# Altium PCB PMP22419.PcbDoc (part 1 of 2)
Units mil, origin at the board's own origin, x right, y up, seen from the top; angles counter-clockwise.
Board outline 4300 x 2100 mil, 4 copper layers (Top Layer, Signal Layer 1, Signal Layer 2, Bottom Layer), stack 66.4 mil thick; 128 components, 54 nets, 301 pads, 317 vias.
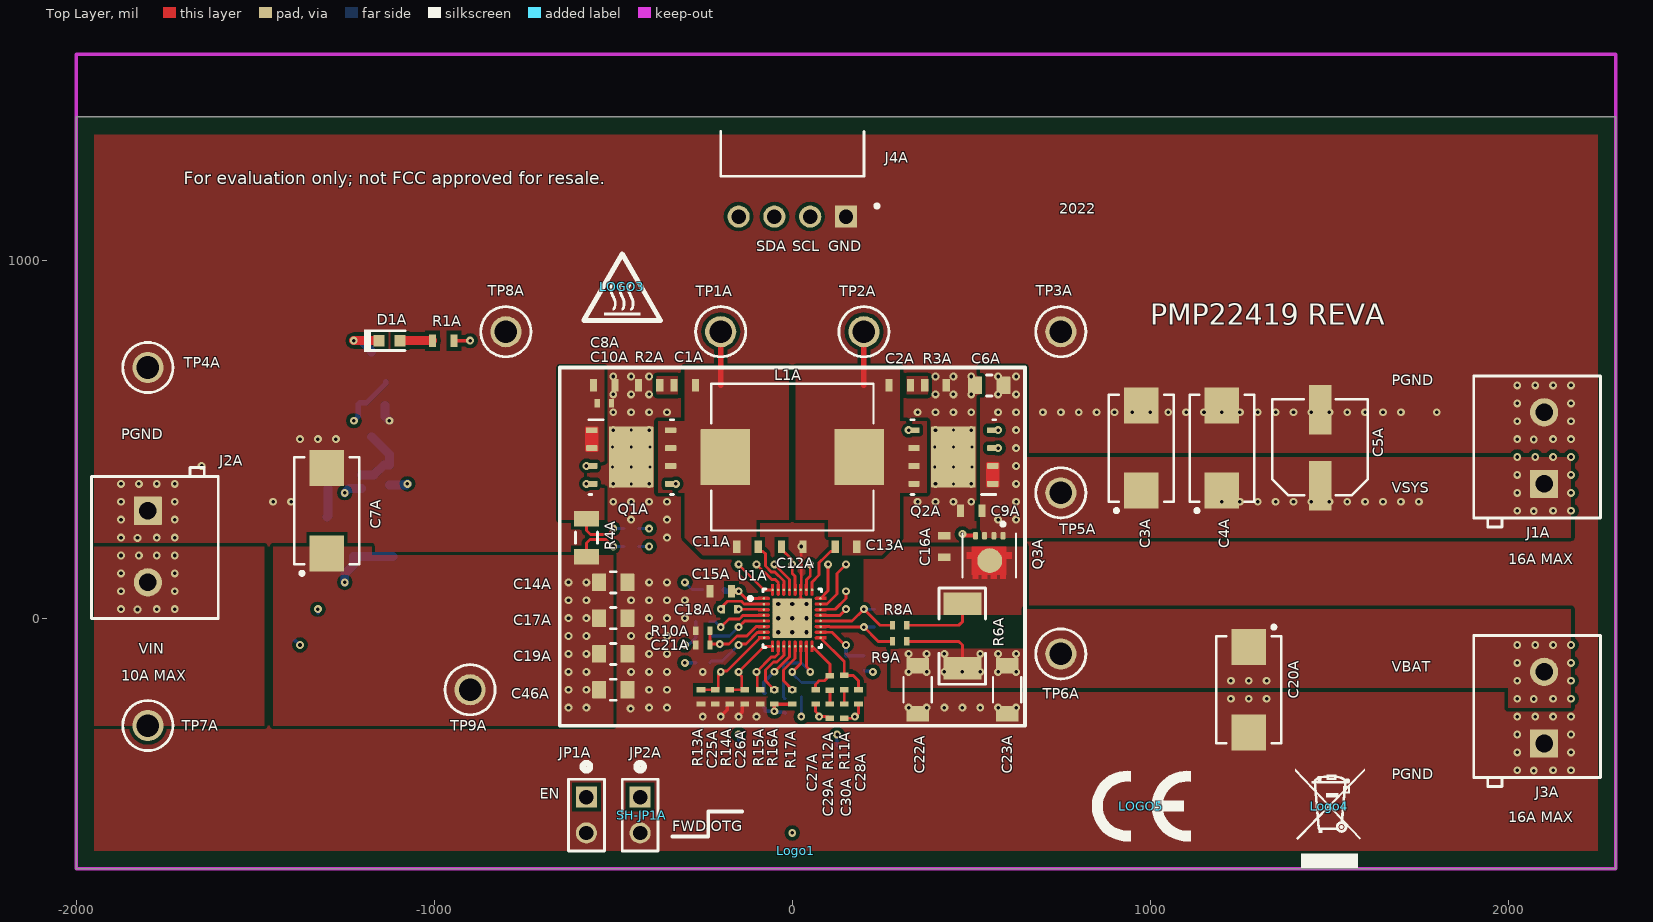
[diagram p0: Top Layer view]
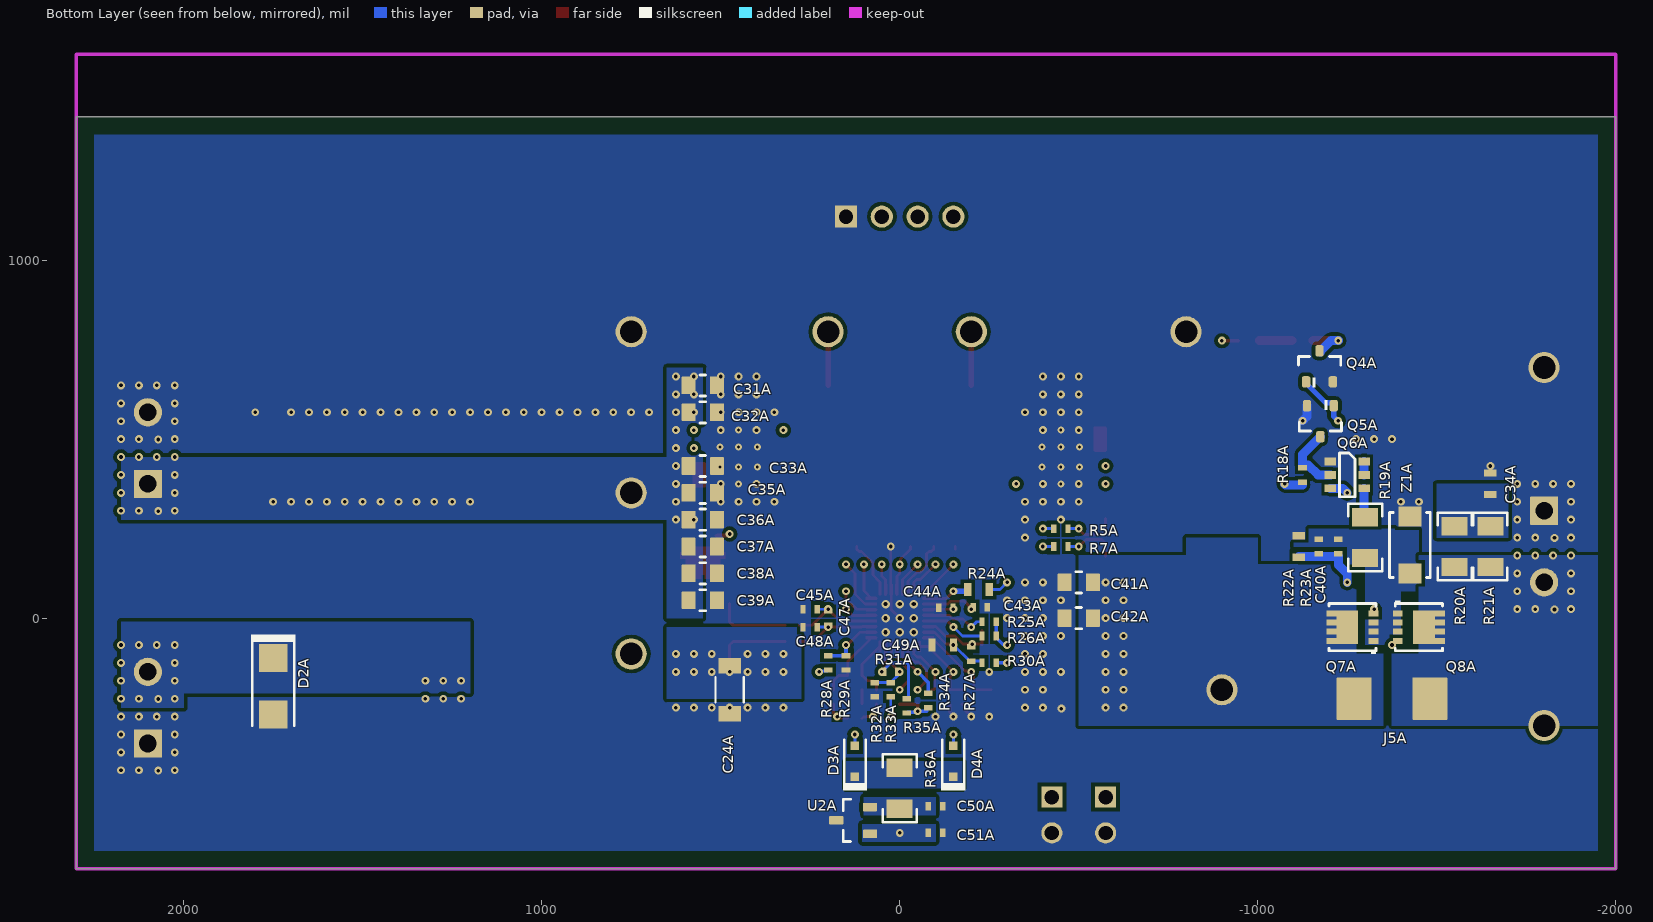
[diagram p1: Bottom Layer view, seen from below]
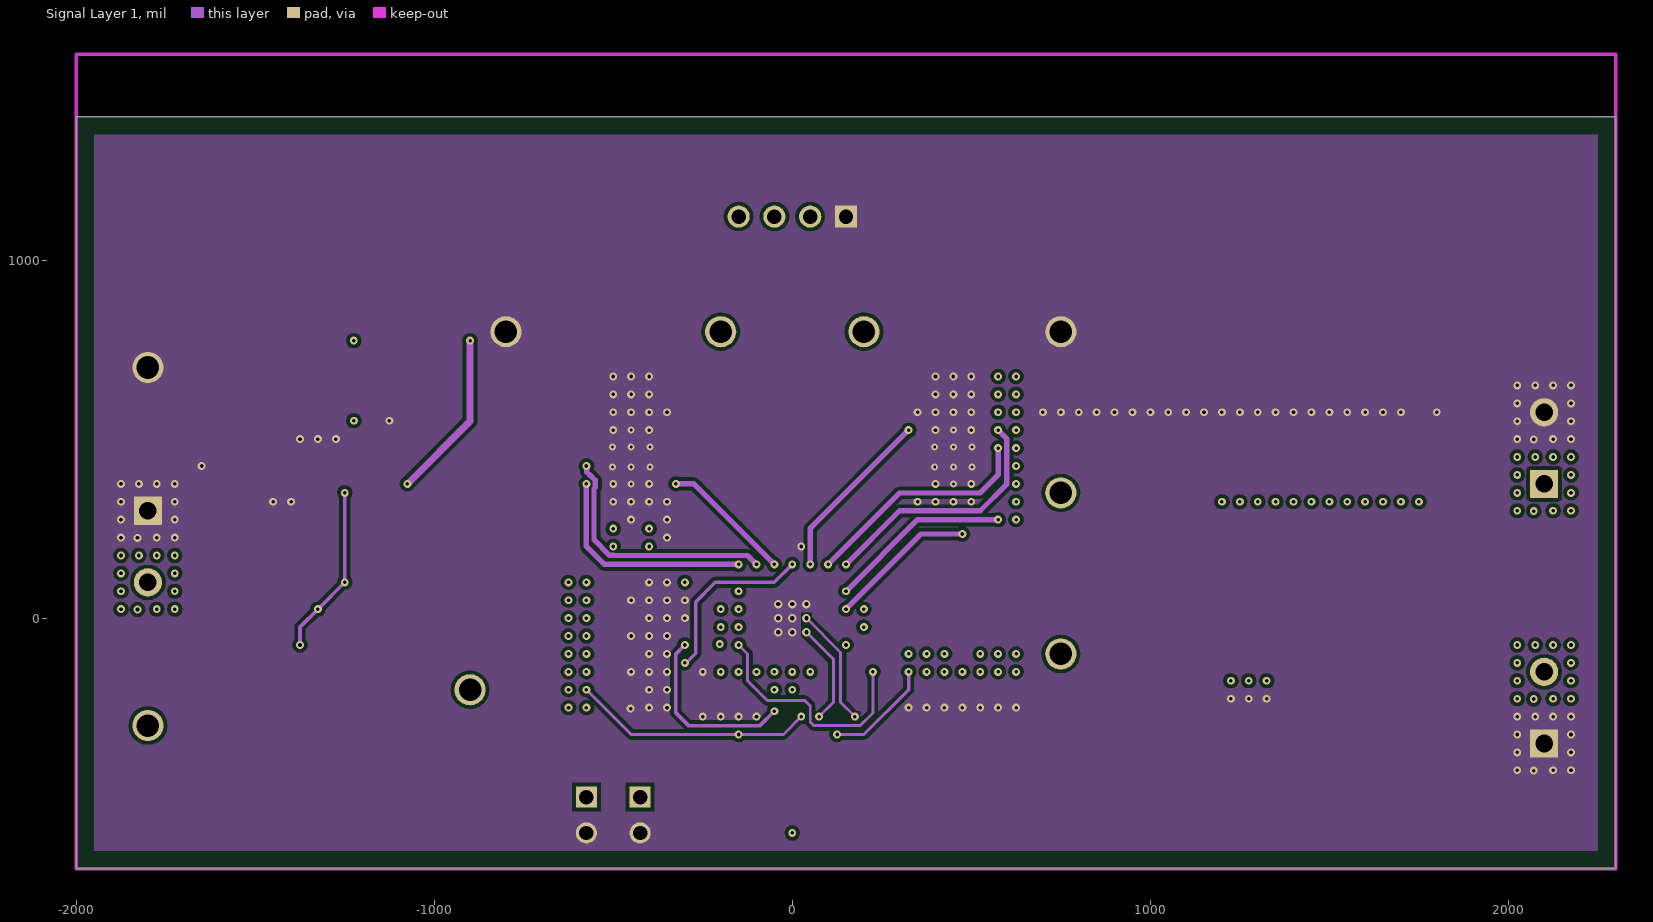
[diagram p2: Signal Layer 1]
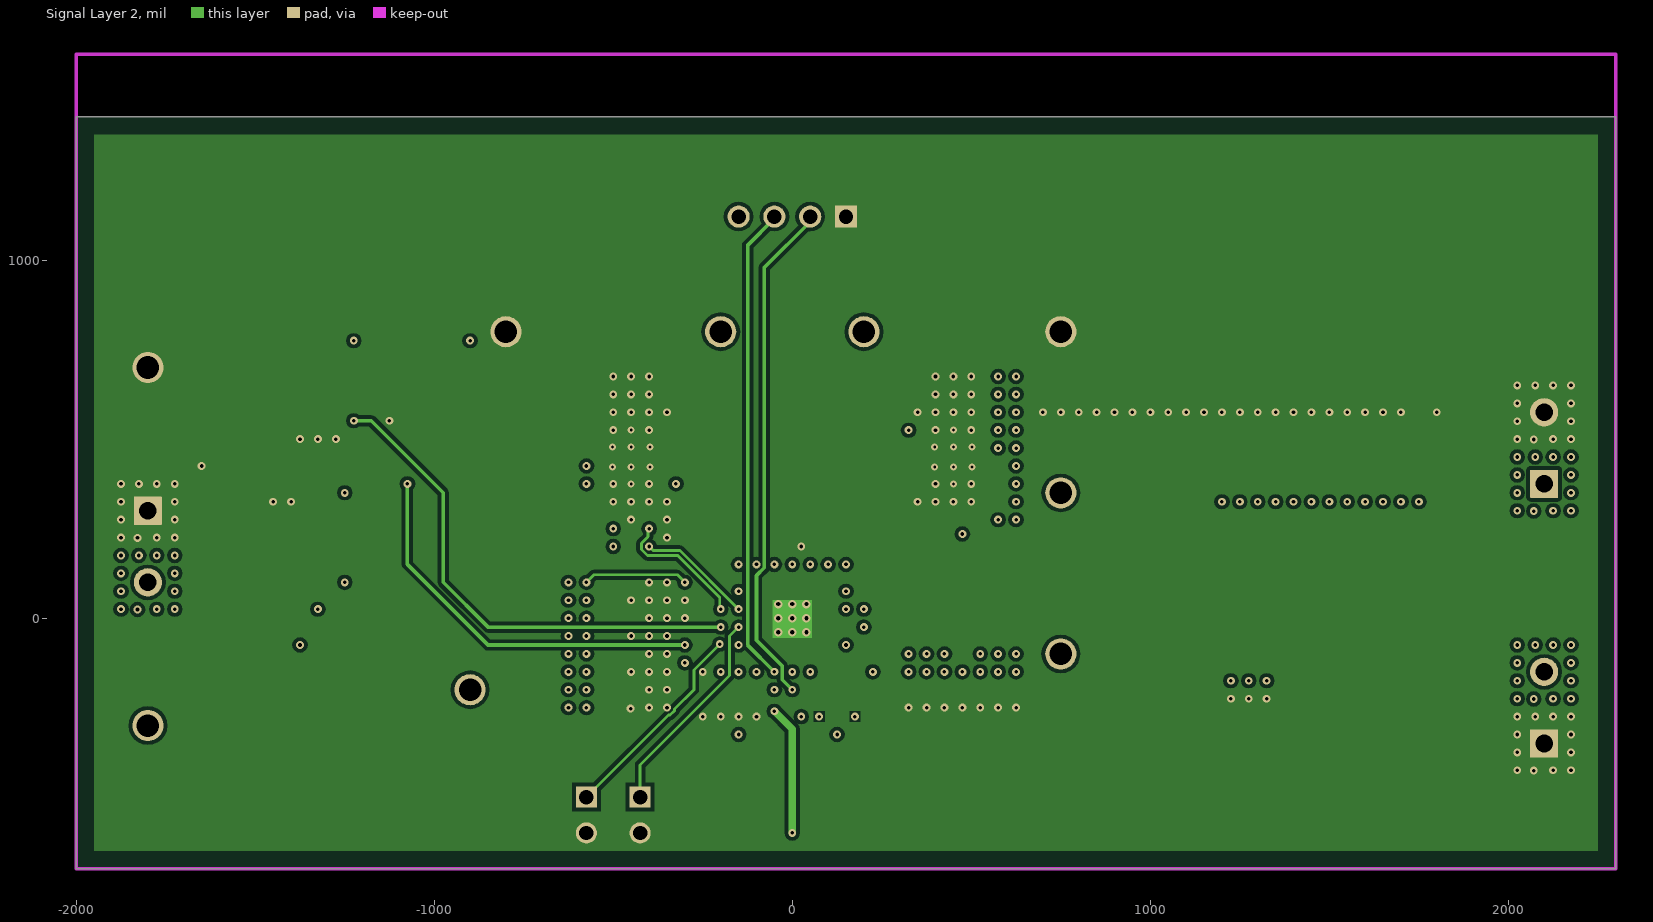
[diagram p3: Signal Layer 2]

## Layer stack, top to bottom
Top Solder: solder mask 0.4, Solder Resist, Dk 3.5
Top Layer: signal copper 2.8
Dielectric1: core 12.6, FR-4 High TG, Dk 4.2
Signal Layer 1: signal copper 2.8
Dielectric 2: prepreg 30, FR-4 High TG, Dk 4.2
Signal Layer 2: signal copper 2.8
Dielectric 3: core 12.6, FR-4 High TG, Dk 4.2
Bottom Layer: signal copper 2.8
Bottom Solder: solder mask 0.4, Solder Resist, Dk 3.5

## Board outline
-2000,1400 -2000,-700 2300,-700 2300,1400

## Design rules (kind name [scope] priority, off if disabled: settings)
AcuteAngle [All] p1: minimum=4.50000000000000E+0001 checktracksonly=FALSE
AssemblyTestPointUsage [All] p1: valid=2
BoardOutlineClearance BoardOutlineClearance_MountingHoles [OnCopper and InComponentClass('Mounting Holes')] p1: gap=39.37 ignorepadtopadclearanceinfootprint=FALSE
BoardOutlineClearance BoardOutlineClearance_Poly [OnCopper and IsPoly] p2: gap=50 ignorepadtopadclearanceinfootprint=FALSE
BoardOutlineClearance [OnCopper and Not InComponentClass('Logo') and not InComponentClass('FiducialMark') and not InRegion(1000,500,4000,800) and not InPoly] p3: gap=75 ignorepadtopadclearanceinfootprint=FALSE
Clearance Clearance_Keepouts [((IsTrack Or IsArc) And Not InPoly) And IsFree and IsKeepOut vs ((IsTrack Or IsArc) And Not InPoly) And IsFree and IsKeepOut] p1: gap=0 ignorepadtopadclearanceinfootprint=FALSE
Clearance Clearance_Poly [InPolygon] p2: gap=10 ignorepadtopadclearanceinfootprint=TRUE
Clearance Clearance_FiducialMark [IsKeepOut and InComponentClass('FiducialMark') vs IsPad and InComponentClass('FiducialMark')] p3: gap=0 ignorepadtopadclearanceinfootprint=FALSE
Clearance [All] p4: gap=6 ignorepadtopadclearanceinfootprint=TRUE
ComponentClearance ComponentClearance_MountingHoles_FiducialMarks [InComponentClass('Mounting Holes') vs InComponentClass('FiducialMark')] p1: gap=50 collisioncheckmode=3 verticalgap=10 showdistances=FALSE
ComponentClearance ComponentClearance_Shunt [InComponentClass('Header') vs InComponentClass('Shunt')] p2: gap=0 collisioncheckmode=3 verticalgap=0 showdistances=FALSE
ComponentClearance ComponentClearance_Logo [InComponentClass('Logo')] p3: gap=50 collisioncheckmode=3 verticalgap=10 showdistances=FALSE
ComponentClearance ComponentClearance_ScrewToNut [(HasFootprint('NY PMS 440 0025 PH')) vs (HasFootprint('Keystone_1902C'))] p4: gap=5 collisioncheckmode=3 verticalgap=10 showdistances=FALSE
ComponentClearance ComponentClearance_MountingHoles [InComponentClass('Mounting Holes')] p5: gap=250 collisioncheckmode=3 verticalgap=100000 showdistances=FALSE
ComponentClearance ComponentClearance_SmallPassives [HasFootprint('0201*') or HasFootprint('0402*') or HasFootprint('0508') or HasFootprint('0603*') or HasFootprint('0612') or HasFootprint('0805*') or HasFootprint('0815*') or HasFootprint('0830*') or HasFootprint('1206*') or HasFootprint('1210*') or HasFootprint('1808*') or HasFootprint('1812*') or HasFootprint('1825*') or HasFootprint('2010*') or HasFootprint('2220*') or HasFootprint('2225*') or HasFootprint('2512*') or HasFootprint('2728*') or HasFootprint('3518*') vs HasFootprint('0201*') or HasFootprint('0402*') or HasFootprint('0508') or HasFootprint('0603*') or HasFootprint('0612') or HasFootprint('0805*') or HasFootprint('0815*') or HasFootprint('0830*') or HasFootprint('1206*') or HasFootprint('1210*') or HasFootprint('1808*') or HasFootprint('1812*') or HasFootprint('1825*') or HasFootprint('2010*') or HasFootprint('2220*') or HasFootprint('2225*') or HasFootprint('2512*') or HasFootprint('2728*') or HasFootprint('3518*')] p6: gap=14.96 collisioncheckmode=3 verticalgap=10 showdistances=FALSE
ComponentClearance ComponentClearance_THtoSMT [IsThruComponent vs IsSMTComponent] p7: gap=40 collisioncheckmode=3 verticalgap=30 showdistances=FALSE
ComponentClearance ComponentClearance_THtoTH [IsThruComponent vs IsThruComponent] p8: gap=30 collisioncheckmode=3 verticalgap=30 showdistances=FALSE
ComponentClearance [All] p9: gap=30 collisioncheckmode=3 verticalgap=10 showdistances=FALSE
DiffPairsRouting [All] p1: maxlimit=100 minlimit=10 mostfreqgap=10 toplayer_minwidth=15 toplayer_maxwidth=15 toplayer_prefwidth=15 midlayer1_minwidth=15 midlayer1_maxwidth=15 midlayer1_prefwidth=15 midlayer2_minwidth=15 midlayer2_maxwidth=15 midlayer2_prefwidth=15 bottomlayer_minwidth=15 bottomlayer_maxwidth=15 bottomlayer_prefwidth=15 maxuncoupledlength=1000
FabricationTestPointUsage TestPointUsage [All] p1: valid=2 allowmultiple=FALSE
FabricationTestpoint Testpoint [All] p1: side=3 testpointundercomponent=TRUE minsize=40 maxsize=100 preferedsize=60 minholesize=0 maxholesize=40 preferedholesize=32 testpointgrid=1 allowsidetop=TRUE allowsidebottom=TRUE usegrid=TRUE gridtolerance=0.01
FanoutControl Fanout_LCC [IsLCC] p1: bgadir=Out bgaviamode=Centered fanoutstyle=Auto fanoutdirection=Alternating viagrid=1 // Fanout_LCC (Default Rule)
FanoutControl Fanout_BGA [IsBGA] p2: bgadir=Out bgaviamode=Centered fanoutstyle=Auto fanoutdirection=Alternating viagrid=1 // Fanout_BGA (Default Rule)
FanoutControl Fanout_Default [All] p4: bgadir=Out bgaviamode=Centered fanoutstyle=Auto fanoutdirection=Alternating viagrid=1 // Fanout_Default (Default Rule)
FanoutControl Fanout_Small [(CompPinCount < 5)] p5: bgadir=Out bgaviamode=Centered fanoutstyle=Auto fanoutdirection=OutThenIn viagrid=1 // Fanout_Small (Default Rule)
HoleSize [All] p1: absolutevalues=TRUE maxlimit=251 minlimit=7.87 maxpercent=80.000 minpercent=20.000
MinimumAnnularRing MinimumAnnularRing_ThermalPadVias [IsVia and InAnyComponent] p1: minimumring=5.91
MinimumAnnularRing [All] p2: minimumring=4
MinimumSolderMaskSliver MinimumSolderMaskSliver_PadPad [IsPad vs IsPad] p1: minsoldermaskwidth=1.5
MinimumSolderMaskSliver MinimumSolderMaskSliver_Via [IsVia] p2: minsoldermaskwidth=1.5
MinimumSolderMaskSliver MinimumSolderMaskSliver_Logo [InComponentClass('Logo') vs InComponentClass('Logo')] p3: minsoldermaskwidth=0.7
MinimumSolderMaskSliver [All] p4: minsoldermaskwidth=3.94
PlaneClearance [All] p1: clearance=10
PlaneConnect [All] p1: planeconnectstyle=Direct reliefexpansion=10 reliefentries=4 reliefconductorwidth=10 reliefairgap=10
PolygonConnect [All] p1: connectstyle=Direct reliefconductorwidth=10 reliefentries=4 polygonreliefangle="90 Angle" airgapwidth=10
RoutingVias ThermalPadVias [IsVia and InAnyComponent] p1: holewidth=7.87 width=19.68 viastyle="Through Hole" minholewidth=7.87 minwidth=19.68 maxholewidth=12.99 maxwidth=23.62
RoutingVias [All] p2: holewidth=10 width=18 viastyle="Through Hole" minholewidth=10 minwidth=18 maxholewidth=40 maxwidth=65
SMDEntry [All] p1 off: side=TRUE corner=FALSE anyangle=FALSE
SMDToCorner [All] p1 off: distance=50000
SilkToBoardRegionClearance [Not ((IsComment or IsDesignator) And (Hide <> 'False')) and not InRegion(1000,500,4000,800)] p1:
SilkToSilkClearance SilkToSilkClearance_Pb-FreeLogo [(HasFootprint('Pb-Free_Overlay_Medium') OR HasFootprint('Pb-Free_Overlay_Small')) vs (HasFootprint('Pb-Free_Overlay_Medium') OR HasFootprint('Pb-Free_Overlay_Small'))] p1: silktosilkclearance=0
SilkToSilkClearance [All] p2: silktosilkclearance=0
SilkToSolderMaskClearance SilkToComponentPadClearance [(IsPad or IsFill or IsRegion) and InAnycomponent] p1: minsilkscreentomaskgap=5 clearancetoexposedcopper=TRUE
SilkToSolderMaskClearance "Silk to Solder Mask Opening" [All] p2: minsilkscreentomaskgap=3.94 clearancetoexposedcopper=FALSE
SolderMaskExpansion [All] p1: expansion=4 istentingtop=FALSE
UnRoutedNet [All] p1: checkbadconnections=TRUE
Width [All] p1: maxlimit=100 minlimit=8 preferedwidth=10 checkconnectedcopper=TRUE
13 further rules are at their usual default settings.

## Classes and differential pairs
component class PMP22419A_MAIN2: C1A C2A C3A C4A C5A C6A C7A C8A C9A C10A C11A C12A C13A C14A C15A C16A C17A C18A C19A C20A C21A C22A C23A C24A C25A C26A C27A C28A C29A C30A C31A C32A C33A C34A C35A C36A C37A C38A C39A C40A C41A C42A C43A C44A C45A C46A C47A C48A C49A C50A C51A D1A D2A D3A D4A J1A J2A J3A J4A J5A JP1A JP2A L1A Q1A Q2A Q3A Q4A Q5A Q6A Q7A Q8A R1A R2A R3A R4A R5A R6A R7A R8A R9A R10A R11A R12A R13A R14A R15A R16A R17A R18A R19A R20A R21A R22A R23A R24A R25A R26A R27A R28A R29A R30A R31A R32A R33A R34A R35A R36A TP1A TP2A TP3A TP4A TP5A TP6A TP7A TP8A TP9A U1A U2A Z1A
component class PMP22419A_Hardware: !PCB1 Logo1 LOGO3 Logo4 LOGO5 SH-JP1A ZZ1 ZZ2 ZZ3 ZZ4
component class AssemblyNote: ZZ1 ZZ2 ZZ3 ZZ4
component class Header: JP1A JP2A
component class Shunt: SH-JP1A

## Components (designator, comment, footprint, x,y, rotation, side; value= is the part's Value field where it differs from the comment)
C1A "Capacitor" 0603S -300,650 r180 top value=330pF
C2A "Capacitor" 0603S 300,650 r0 top value=330pF
C3A "T521D336M035ATE065" 7343-31 975,475 r90 top value=33uF
C4A "T521D336M035ATE065" 7343-31 1200,475 r90 top value=33uF
C5A "Cap_Polarized" CAPSMT_62_F61 1475,475 r90 top value=47uF
C6A "Capacitor" 0805_HV1 550,650 r180 top value=10uF
C7A "T521D336M035ATE065" 7343-31 -1300,300 r90 top value=33uF
C8A "GRM188R71H103KA01D" 0603S -525,650 r0 top value=0.01uF
C9A "GRM188R71H103KA01D" 0603S 500,300 r180 top value=0.01uF
C10A "C1005NP01H102J050BA" 0402S -525,600 r0 top value=1000pF
C11A "Capacitor" 0603S -125,200 r180 top value=0.047uF
C12A "Capacitor" 0603S 0,200 r0 top value=2.2uF
C13A "Capacitor" 0603S 150,200 r0 top value=0.047uF
C14A "Capacitor" 0805_HV1 -500,100 r0 top value=10uF
C15A "C1608X7R1H474K080AC" 0603S -200,75 r180 top value=0.47uF
C16A "Capacitor" 0603S 425,200 r90 top value=1uF
C17A "Capacitor" 0805_HV1 -500,0 r0 top value=10uF
C18A "0402B103K500CT" 0402S -175,25 r180 top value=0.01uF
C19A "Capacitor" 0805_HV1 -500,-100 r0 top value=10uF
C20A "T521D336M035ATE065" 7343-31 1275,-200 r270 top value=33uF
C21A "04025A101FAT2A" 0402S -250,-75 r180 top value=100pF
C22A "Capacitor" 1206_180 350,-200 r270 top value=10uF
C23A "Capacitor" 1206_180 600,-200 r270 top value=10uF
C24A "Capacitor" 1206_180 475,-200 r270 bottom value=10uF
C25A "04025A101FAT2A" 0402S -215,-220 r270 top value=100pF
C26A "04025A101FAT2A" 0402S -133.19,-220 r270 top value=100pF
C27A "Capacitor" 0402S 65,-220 r90 top value=33pF
C28A "Capacitor" 0402S 185,-220 r270 top value=15pF
C29A "GRM155R71H332KA01D" 0402S 105,-260 r90 top value=3300pF
C30A "C0402C122J5GACTU" 0402S 145,-260 r270 top value=1200pF
C31A "Capacitor" 0805_HV1 550,650 r180 bottom value=10uF
C32A "Capacitor" 0805_HV1 550,575 r180 bottom value=10uF
C33A "Capacitor" 0805_HV1 550,425 r180 bottom value=10uF
C34A "Capacitor" 0603S -1650,375 r90 bottom value=1uF
C35A "Capacitor" 0805_HV1 550,350 r180 bottom value=10uF
C36A "Capacitor" 0805_HV1 550,275 r180 bottom value=10uF
C37A "Capacitor" 0805_HV1 550,200 r180 bottom value=10uF
C38A "Capacitor" 0805_HV1 550,125 r180 bottom value=10uF
C39A "Capacitor" 0805_HV1 550,50 r180 bottom value=10uF
C40A "0402BB104KW500" 0402S -1225,200 r90 bottom value=0.1uF
C41A "Capacitor" 0805_HV1 -500,100 r0 bottom value=10uF
C42A "Capacitor" 0805_HV1 -500,0 r0 bottom value=10uF
C43A "CGA2B3X7R1H333K050BB" 0402S -225,30 r180 bottom value=0.033uF
C44A "CGA2B3X7R1H333K050BB" 0402S -129,29.18 r0 bottom value=0.033uF
C45A "GRM155R71H183KA12D" 0402S 250,25 r0 bottom value=0.018uF
C46A "Capacitor" 0805_HV1 -500,-200 r0 top value=10uF
C47A "CGA2B3X7R1H683K050BB" 0402S 200,0 r90 bottom value=0.068uF
C48A "GRM155R71H183KA12D" 0402S 250,-25 r0 bottom value=0.018uF
C49A "Capacitor" 0603S -120,-75 r0 bottom value=1uF
C50A "0402BB104KW500" 0402S -100,-525 r0 bottom value=0.1uF
C51A "0402BB104KW500" 0402S -100,-600 r0 bottom value=0.1uF
D1A "LTST-C190GKT" LED_LTST-C190 -1125,775 r180 top value=Green
D2A "20V" SMA 1750,-190 r270 bottom
D3A "BAT54HT1G" SOD-323 125,-400 r90 bottom value=30V
D4A "BAT54HT1G" SOD-323 -150,-400 r90 bottom value=30V
J1A "Receptacle_2x1" On-Shore_ED120_2DS 2100,475 r90 top
J2A "Receptacle_2x1" On-Shore_ED120_2DS -1800,200 r270 top
J3A "Receptacle_2x1" On-Shore_ED120_2DS 2100,-250 r90 top
J4A "22-05-3041" FP-22-05-3041_HDR4-MFG 0,1400 r180 top
J5A "5102" Keystone_5102 -1375,-225 r0 bottom
JP1A "Header_2x1" CONN_5-146261-1 -575,-550 r270 top
JP2A "Header_2x1" CONN_5-146261-1 -425,-550 r270 top
L1A "Inductor_Iron" FP-BMRHDY1010302R2MA1_SMT_IND_11MM2_10MM1-MFG 0,450 r0 top
Logo1 "FCC disclaimer" FCC_disclaimer 10,-650 r0 top
LOGO3 "CAUTION HOT SURFACE" IEC_HotSurface_Small -475,925 r0 top
Logo4 "WEEE logo" WEEE_Minimum 1500,-525 r0 top
LOGO5 "CE Mark" CE_Mark_5mm 975,-525 r0 top
Q1A "CSD87355Q5D" DQY0008A -450,450 r0 top value=30V
Q2A "CSD87355Q5D" DQY0008A 450,450 r180 top value=30V
Q3A "AONR21307" FP-AONR21307_DFN8-MFG 550,175 r180 top
Q4A "MOSFET_N_D3G1S2" SOT-23L -1172.6,703.31 r90 bottom value=60V
Q5A "MOSFET_N_D3G1S2" SOT-23L -1175,550 r270 bottom value=60V
Q6A "DCX124EK-7-F" SC-74R -1250,400 r180 bottom value="50 V"
Q7A "DMP3035SFG-7" PowerDI3333-8 -1264.76,-25 r0 bottom value=-30V
Q8A "DMP3035SFG-7" PowerDI3333-8 -1450,-25 r180 bottom value=-30V
R1A "Resistor" 0603S -975,775 r0 top value=2.00k
R2A "Resistor" 0603S -400,650 r0 top value=56
R3A "Resistor" 0603S 400,650 r180 top value=56
R4A "WSLP12065L000FEA" 1206L -575,225 r90 top value=0.005
R5A "CRCW04024R99FKED" 0402S -450,250 r180 bottom value=4.99
R6A "CSNL2010FT5L00" 2010 475,-50 r270 top value=0.005
R7A "CRCW04024R99FKED" 0402S -450,200 r180 bottom value=4.99
R8A "CRCW040210R0FKED" 0402S 300,-20 r0 top value=10.0
R9A "CRCW040210R0FKED" 0402S 300,-65 r0 top value=10.0
R10A "RC0402FR-07220KL" 0402S -250,-35 r180 top value=220k
R11A "Resistor" 0402S 145,-180 r270 top value=10.0k
R12A "CRCW040216K9FKED" 0402S 105,-181.1 r90 top value=16.9k
R13A "CRCW0402105KFKED" 0402S -255,-220 r90 top value=105k
R14A "CRCW0402100KFKED" 0402S -175,-220 r90 top value=100k
R15A "CRCW040230K1FKED" 0402S -90,-220 r270 top value=30.1k
R16A "CRCW040210K0FKED" 0402S -50,-220 r90 top value=10.0k
R17A "CRCW040210K0FKED" 0402S 0,-220 r270 top value=10.0k
R18A "CRCW040210K0FKED" 0402S -1125,400 r270 bottom value=10.0k
R19A "ERJ-8ENF10R0V" 1206 -1300,225 r270 bottom value=10.0
R20A "Resistor" 1206 -1550,200 r270 bottom value=3.9
R21A "Resistor" 1206 -1650,200 r270 bottom value=3.9
R22A "CRCW060320K0FKEA" 0603S -1115,200 r270 bottom value=20.0k
R23A "CRCW0402100KFKED" 0402S -1170,200 r90 bottom value=100k
R24A "CRCW06031R00JNEA" 0603S -220,80 r0 bottom value=1.0
R25A "CRCW040210K0FKED" 0402S -250,-10 r180 bottom value=10.0k
R26A "CRCW040210K0FKED" 0402S -250,-50 r0 bottom value=10.0k
R27A "CRCW0402383KFKED" 0402S -200,-100 r270 bottom value=383k
R28A "RC0402FR-0733KL" 0402S 200,-125 r270 bottom value=33.0k
R29A "CRCW0402100KFKED" 0402S 150,-125 r90 bottom value=100k
R30A "CRCW040210R0FKED" 0402S -250,-125 r0 bottom value=10.0
R31A "CRCW04022M00JNED" 0402S 25,-150 r0 bottom value=2.0Meg
R32A "CRCW0402100KFKED" 0402S 70,-200 r90 bottom value=100k
R33A "CRCW0402100KFKED" 0402S 25,-200 r270 bottom value=100k
R34A "CRCW040210K0FKED" 0402S -80,-230 r270 bottom value=10.0k
R35A "CRCW040210K0FKED" 0402S -20,-245 r90 bottom value=10.0k
R36A "ERJ-8ENF10R0V" 1206 0,-475 r90 bottom value=10.0
SH-JP1A "SNT-100-BK-G" SNT-100-BK-G -420,-550 r90 top value=1x2
TP1A "5012" Keystone5012 -200,800 r90 top
TP2A "5012" Keystone5012 200,800 r90 top
TP3A "5011" Keystone5011 750,800 r180 top
TP4A "5011" Keystone5011 -1800,700 r180 top
TP5A "5010" Keystone5010 750,350 r0 top
TP6A "5010" Keystone5010 750,-100 r0 top
TP7A "5010" Keystone5010 -1800,-300 r0 top
TP8A "5011" Keystone5011 -800,800 r180 top
TP9A "5010" Keystone5010 -900,-200 r0 top
U1A "BQ25720RSN" RSN0032B-MFG 0,0 r0 top
U2A "PM-REG-LM3480-SOT3" DBZ0003A_N 130,-565 r0 bottom
Z1A "SMAJ26CA" SMA_Bi -1425,204.33 r90 bottom value=26V
ZZ1 "This Assembly Note is for PCB labels only" AssemblyNoteLabel -1785,2138 r0 top
ZZ2 "These assemblies are ESD sensitive, ESD precautions shall be observed." AssemblyNote -1785,2029.11 r0 top
ZZ3 "These assemblies must be clean and free from flux and all contaminants. Use of no clean flux is not acceptable." AssemblyNote -1785,1940.56 r0 top
ZZ4 "These assemblies must comply with workmanship standards IPC-A-610 Class 2, unless otherwise specified." AssemblyNote -1785,1852 r0 top

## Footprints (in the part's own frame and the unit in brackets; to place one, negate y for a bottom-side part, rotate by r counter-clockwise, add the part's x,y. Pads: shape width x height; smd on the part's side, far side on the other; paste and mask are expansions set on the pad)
0402S [mil] "Based on C0402S footprint from PADS legacy"
  rect 15x24 smd: 1(-20,0) 2(20,0)
  body extent -22,-12 22,12, height 24
0603S [mil]
  rect 20x35 smd: 1(-30,0) 2(30,0)
  body extent -34,-19 34,19, height 39
0805_HV1 [mm] "Custom footprint based on analyzing multiple manufacturer recommendations"
  rrect10% 1x1.25 smd: 1(-1,0) 2(1,0)
  silkscreen extent -0.2,-0.75 0.2,0.75, body extent -1.1,-0.72 1.1,0.73, height 1.45
1206 [mm] "1206 from SM-752 data"
  rect 1.3x1.85 smd: 1(-1.45,0) 2(1.45,0)
  silkscreen extent -2.4,-1.21 2.4,1.21, body extent -1.7,-0.9 1.7,0.9, height 1.35
1206_180 [mm] "1206_180"
  rect 1.1x1.6 smd: 1(-1.7,0) 2(1.7,0)
  silkscreen extent -0.9,-1 0.9,1, body extent -1.75,-0.95 1.75,0.95, height 1.8
1206L [mm] "1206 from SM-752 data"
  rect 1.1x1.75 smd: 1(-1.35,0) 2(1.35,0)
  silkscreen extent -0.4,-0.77 0.4,0.77, body extent -1.7,-0.9 1.7,0.9, height 1.35
2010 [mm] "Chip Capacitor, Body 5.08x2.54mm, IPC Medium Density"
  rect 1.6x2.7 smd: 1(-2.3,0) 2(2.3,0)
  silkscreen extent -3.42,-1.65 3.42,1.65, body extent -2.73,-1.45 2.73,1.45, height 1.66
7343-31 [mm] "Medium Density based on Kemet T495 dimensions"
  rect 2.55x2.45 smd: 1(-3.025,0) 2(3.025,0)
  silkscreen extent -4.56,-2.3 3.8,2.3, body extent -3.8,-2.3 3.8,2.3, height 3.1
AssemblyNote [mil] "Assembly Note"
AssemblyNoteLabel [mil] "Assembly Note for PCB Labels"
CAPSMT_62_F61 [mm] "6.3 x 5.8mm:  Chemi-Con F61"
  rect 3.5x1.6 smd: 1(-2.675,0.025) 2(2.725,0.025)
  silkscreen extent -3.34,-3.38 3.46,3.42, body extent -3.37,-3.38 3.46,3.43, height 6.1
CE_Mark_5mm [mil] "Minimum text height for CE Mark"
  silkscreen extent -138,-98 138,98
CONN_5-146261-1 [mm] "Sullins"
  rect 1.5x1.5 hole 1.02: 1(-1.27,0)
  round 1.5 hole 1.02: 2(1.27,0)
  silkscreen extent -3.68,-1.27 2.54,1.27, body extent -2.51,-1.27 2.51,1.27, height 10.87
DBZ0003A_N [mm] "SOT23, 3-Leads, Body 2.9x1.3mm, Pitch 0.95mm, Lead Span 2.4mm, IPC Medium Density"
  rrect17% 1x0.6 smd: 1(-1.2,0.95) 2(-1.2,-0.95) 3(1.2,0)
  silkscreen extent 0.2,-1.5 0.7,1.5, body extent -1.26,-1.46 1.26,1.46, height 0.98
DQY0008A [mm] "LSON-CLIP-8"
  rrect24% 0.81x0.41 smd mask+0: 1(-2.795,1.905) 2(-2.795,0.635)
  rrect24% 0.81x0.41 smd: 3(-2.795,-0.635) 4(-2.795,-1.905) 5(2.795,-1.905) 6(2.795,-0.635) 8(2.795,1.905)
  rrect24% 0.81x0.41 smd mask+0.102: 7(2.795,0.635)
  rrect3% 3.156x4.319 smd paste-2.217: 9(0,0)
  Top Layer region: -3.25,0.48 -3.25,2.06 -3.237,2.11 -3.2,2.147 -3.15,2.16 -3.15,2.16 -2.44,2.16 -2.402,2.152 -2.369,2.131 -2.348,2.098 -2.34,2.06 -2.34,2.06 -2.34,0.48 -2.348,0.442 -2.369,0.409 -2.402,0.388 -2.44,0.38 -2.44,0.38 -3.15,0.38 -3.188,0.388 -3.221,0.409 -3.242,0.442 -3.25,0.48
  silkscreen extent -3,-2.65 3,2.65, body extent -3,-2.5 3,2.5, height 1.6
FCC_disclaimer [mil]
FP-22-05-3041_HDR4-MFG [mm]
  rrect6% 1.57x1.57 hole 1.02 paste-1000 mask+0: 1(-3.81,7.073)
  round 1.57 hole 1.02 paste-1000 mask+0: 2(-1.27,7.073) 3(1.27,7.073) 4(3.81,7.073)
  silkscreen extent -6.13,1.03 5.08,6.44, body extent -5.18,-6.28 5.18,7.96, height 0.25
FP-AONR21307_DFN8-MFG [mm]
  rrect29% 0.35x0.5 smd paste+0 mask+0: 1(-0.975,-1.4) 2(-0.325,-1.4) 3(0.325,-1.4) 4(0.975,-1.4)
  round 1.769 smd paste+0 mask+0: 5-6-7-8(-0.038,0.367)
  Top Layer region: -1.225,-0.63 -1.225,-0.215 -1.605,-0.215 -1.605,0.215 -1.225,0.215 -1.225,1.35 -1.175,1.35 -1.175,1.65 -0.775,1.65 -0.775,1.35 -0.525,1.35 -0.525,1.65 -0.125,1.65 -0.125,1.35 0.125,1.35 0.125,1.65 0.525,1.65 0.525,1.35 0.775,1.35 0.775,1.65 1.175,1.65 1.175,1.35 1.225,1.35 1.225,0.215 1.605,0.215 1.605,-0.215 1.225,-0.215 1.225,-0.63
  silkscreen extent -1.9,-2.35 1.9,1.55, body extent -1.71,-1.75 1.71,1.75, height 0.25
FP-BMRHDY1010302R2MA1_SMT_IND_11MM2_10MM1-MFG [mm]
  rrect3% 3.5x4 smd paste+0 mask+0: 1(-4.75,0) 2(4.75,0)
  silkscreen extent -5.75,-5.2 5.75,5.2, body extent -6.6,-5.3 6.6,5.3, height 0.25
IEC_HotSurface_Small [mil]
  silkscreen extent -107,-93 107,92
Keystone5010 [mil] "Keystone Multipurpose loops"
  round 87 hole 63: 1(0,0)
  silkscreen extent -70,-70 70,70, body extent -63,-63 63,62, height 319
Keystone5011 [mil] "Keystone Multipurpose loops"
  round 87 hole 63: 1(0,0)
  silkscreen extent -70,-70 70,70, body extent -63,-63 63,62, height 319
Keystone5012 [mil] "Keystone Multipurpose loops"
  round 87 hole 63: 1(0,0)
  silkscreen extent -70,-70 70,70, body extent -63,-63 63,62, height 319
Keystone_5102 [mm] "Shorting Jumper, 5.375mm, 2 Position, SMT"
  rrect4% 2.475x3 smd: 1(-2.688,0) 2(2.688,0)
  body extent -3.42,-1.19 3.43,1.35, height 1
LED_LTST-C190 [mm] "Lite-On"
  rect 0.8x0.8 smd: 1(-0.75,0) 2(0.75,0)
  silkscreen extent -1.1,-0.8 1.8,0.8, body extent -0.85,-0.45 0.85,0.45, height 0.9
On-Shore_ED120_2DS [mm] "ONSHORE"
  rrect5% 2x2 hole 1.25: 1(-2.54,0)
  round 2 hole 1.25: 2(2.54,0)
  silkscreen extent -5.6,-4 5.12,5, body extent -5.78,-4 5.08,5, height 13
PowerDI3333-8 [mm] "SMD, 8-Leads, Body 3.3x3.3mm, Pitch 0.65mm"
  rect 0.7x0.42 smd: 1(-1.5,0.975) 2(-1.5,0.325) 3(-1.5,-0.325) 4(-1.5,-0.975) 5(1.5,-0.975) 6(1.5,-0.325) 7(1.5,0.325) 8(1.5,0.975)
  rect 1.55x2.37 smd: 9(0.375,0)
  silkscreen extent -1.68,-1.68 1.68,1.9, body extent -1.68,-1.68 1.68,1.68, height 0.86
RSN0032B-MFG [mm]
  round 0.18 smd paste+0 mask+0: 1(-2.01,1.4) 2(-2.01,1) 3(-2.01,0.6) 4(-2.01,0.2) 5(-2,-0.2) 6(-2,-0.6) 7(-2,-1) 8(-2,-1.4) 9(-1.4,-2.01) 10(-1,-2.01) 11(-0.6,-2.01) 12(-0.2,-2.01) 13(0.2,-2) 14(0.6,-2) 15(1,-2) 16(1.4,-2) 17(2.01,-1.4) 18(2.01,-1) 19(2.01,-0.6) 20(2.01,-0.2) 21(2,0.2) 22(2,0.6) 23(2,1) 24(2,1.4) 25(1.4,2.01) 26(1,2.01) 27(0.6,2.01) 28(0.2,2.01) 29(-0.2,2) 30(-0.6,2) 31(-1,2) 32(-1.4,2)
  rrect4% 2.8x2.8 smd paste-1000 mask+0: 33(0,0)
  Top Layer region: -2.4,1.5 -1.7,1.5 -1.662,1.492 -1.629,1.471 -1.608,1.438 -1.6,1.4 -1.6,1.4 -1.608,1.362 -1.629,1.329 -1.662,1.308 -1.7,1.3 -1.7,1.3 -2.4,1.3
  Top Layer region: -2.4,1.1 -1.7,1.1 -1.662,1.092 -1.629,1.071 -1.608,1.038 -1.6,1 -1.6,1 -1.608,0.962 -1.629,0.929 -1.662,0.908 -1.7,0.9 -1.7,0.9 -2.4,0.9
  Top Layer region: -2.4,0.7 -1.7,0.7 -1.662,0.692 -1.629,0.671 -1.608,0.638 -1.6,0.6 -1.6,0.6 -1.608,0.562 -1.629,0.529 -1.662,0.508 -1.7,0.5 -1.7,0.5 -2.4,0.5
  Top Layer region: -2.4,0.3 -1.7,0.3 -1.662,0.292 -1.629,0.271 -1.608,0.238 -1.6,0.2 -1.6,0.2 -1.608,0.162 -1.629,0.129 -1.662,0.108 -1.7,0.1 -1.7,0.1 -2.4,0.1
  Top Layer region: -2.4,-0.1 -1.7,-0.1 -1.662,-0.108 -1.629,-0.129 -1.608,-0.162 -1.6,-0.2 -1.6,-0.2 -1.608,-0.238 -1.629,-0.271 -1.662,-0.292 -1.7,-0.3 -1.7,-0.3 -2.4,-0.3
  Top Layer region: -2.4,-0.5 -1.7,-0.5 -1.662,-0.508 -1.629,-0.529 -1.608,-0.562 -1.6,-0.6 -1.6,-0.6 -1.608,-0.638 -1.629,-0.671 -1.662,-0.692 -1.7,-0.7 -1.7,-0.7 -2.4,-0.7
  Top Layer region: -2.4,-0.9 -1.7,-0.9 -1.662,-0.908 -1.629,-0.929 -1.608,-0.962 -1.6,-1 -1.6,-1 -1.608,-1.038 -1.629,-1.071 -1.662,-1.092 -1.7,-1.1 -1.7,-1.1 -2.4,-1.1
  Top Layer region: -2.4,-1.3 -1.7,-1.3 -1.662,-1.308 -1.629,-1.329 -1.608,-1.362 -1.6,-1.4 -1.6,-1.4 -1.613,-1.45 -1.65,-1.487 -1.7,-1.5 -1.7,-1.5 -2.4,-1.5
  Top Layer region: -1.5,-2.4 -1.5,-1.7 -1.492,-1.662 -1.471,-1.629 -1.438,-1.608 -1.4,-1.6 -1.4,-1.6 -1.362,-1.608 -1.329,-1.629 -1.308,-1.662 -1.3,-1.7 -1.3,-1.7 -1.3,-2.4
  Top Layer region: -1.1,-2.4 -1.1,-1.7 -1.092,-1.662 -1.071,-1.629 -1.038,-1.608 -1,-1.6 -1,-1.6 -0.962,-1.608 -0.929,-1.629 -0.908,-1.662 -0.9,-1.7 -0.9,-1.7 -0.9,-2.4
  Top Layer region: -0.7,-2.4 -0.7,-1.7 -0.692,-1.662 -0.671,-1.629 -0.638,-1.608 -0.6,-1.6 -0.6,-1.6 -0.562,-1.608 -0.529,-1.629 -0.508,-1.662 -0.5,-1.7 -0.5,-1.7 -0.5,-2.4
  Top Layer region: -0.3,-2.4 -0.3,-1.7 -0.292,-1.662 -0.271,-1.629 -0.238,-1.608 -0.2,-1.6 -0.2,-1.6 -0.162,-1.608 -0.129,-1.629 -0.108,-1.662 -0.1,-1.7 -0.1,-1.7 -0.1,-2.4
  Top Layer region: 0.1,-2.4 0.1,-1.7 0.108,-1.662 0.129,-1.629 0.162,-1.608 0.2,-1.6 0.2,-1.6 0.238,-1.608 0.271,-1.629 0.292,-1.662 0.3,-1.7 0.3,-1.7 0.3,-2.4
  Top Layer region: 0.5,-2.4 0.5,-1.7 0.508,-1.662 0.529,-1.629 0.562,-1.608 0.6,-1.6 0.6,-1.6 0.638,-1.608 0.671,-1.629 0.692,-1.662 0.7,-1.7 0.7,-1.7 0.7,-2.4
  Top Layer region: 0.9,-2.4 0.9,-1.7 0.908,-1.662 0.929,-1.629 0.962,-1.608 1,-1.6 1,-1.6 1.038,-1.608 1.071,-1.629 1.092,-1.662 1.1,-1.7 1.1,-1.7 1.1,-2.4
  Top Layer region: 1.3,-2.4 1.3,-1.7 1.308,-1.662 1.329,-1.629 1.362,-1.608 1.4,-1.6 1.4,-1.6 1.438,-1.608 1.471,-1.629 1.492,-1.662 1.5,-1.7 1.5,-1.7 1.5,-2.4
  Top Layer region: 2.4,-1.5 1.7,-1.5 1.662,-1.492 1.629,-1.471 1.608,-1.438 1.6,-1.4 1.6,-1.4 1.608,-1.362 1.629,-1.329 1.662,-1.308 1.7,-1.3 1.7,-1.3 2.4,-1.3
  Top Layer region: 2.4,-1.1 1.7,-1.1 1.662,-1.092 1.629,-1.071 1.608,-1.038 1.6,-1 1.6,-1 1.608,-0.962 1.629,-0.929 1.662,-0.908 1.7,-0.9 1.7,-0.9 2.4,-0.9
  Top Layer region: 2.4,-0.7 1.7,-0.7 1.662,-0.692 1.629,-0.671 1.608,-0.638 1.6,-0.6 1.6,-0.6 1.608,-0.562 1.629,-0.529 1.662,-0.508 1.7,-0.5 1.7,-0.5 2.4,-0.5
  Top Layer region: 2.4,-0.3 1.7,-0.3 1.662,-0.292 1.629,-0.271 1.608,-0.238 1.6,-0.2 1.6,-0.2 1.608,-0.162 1.629,-0.129 1.662,-0.108 1.7,-0.1 1.7,-0.1 2.4,-0.1
  Top Layer region: 2.4,0.1 1.7,0.1 1.662,0.108 1.629,0.129 1.608,0.162 1.6,0.2 1.6,0.2 1.608,0.238 1.629,0.271 1.662,0.292 1.7,0.3 1.7,0.3 2.4,0.3
  Top Layer region: 2.4,0.5 1.7,0.5 1.662,0.508 1.629,0.529 1.608,0.562 1.6,0.6 1.6,0.6 1.608,0.638 1.629,0.671 1.662,0.692 1.7,0.7 1.7,0.7 2.4,0.7
  Top Layer region: 2.4,0.9 1.7,0.9 1.662,0.908 1.629,0.929 1.608,0.962 1.6,1 1.6,1 1.608,1.038 1.629,1.071 1.662,1.092 1.7,1.1 1.7,1.1 2.4,1.1
  Top Layer region: 2.4,1.3 1.7,1.3 1.662,1.308 1.629,1.329 1.608,1.362 1.6,1.4 1.6,1.4 1.608,1.438 1.629,1.471 1.662,1.492 1.7,1.5 1.7,1.5 2.4,1.5
  Top Layer region: 1.5,2.4 1.5,1.7 1.492,1.662 1.471,1.629 1.438,1.608 1.4,1.6 1.4,1.6 1.362,1.608 1.329,1.629 1.308,1.662 1.3,1.7 1.3,1.7 1.3,2.4
  Top Layer region: 1.1,2.4 1.1,1.7 1.092,1.662 1.071,1.629 1.038,1.608 1,1.6 1,1.6 0.962,1.608 0.929,1.629 0.908,1.662 0.9,1.7 0.9,1.7 0.9,2.4
  Top Layer region: 0.7,2.4 0.7,1.7 0.687,1.65 0.65,1.613 0.6,1.6 0.6,1.6 0.562,1.608 0.529,1.629 0.508,1.662 0.5,1.7 0.5,1.7 0.5,2.4
  Top Layer region: 0.3,2.4 0.3,1.7 0.292,1.662 0.271,1.629 0.238,1.608 0.2,1.6 0.2,1.6 0.162,1.608 0.129,1.629 0.108,1.662 0.1,1.7 0.1,1.7 0.1,2.4
  Top Layer region: -0.1,2.4 -0.1,1.7 -0.108,1.662 -0.129,1.629 -0.162,1.608 -0.2,1.6 -0.2,1.6 -0.238,1.608 -0.271,1.629 -0.292,1.662 -0.3,1.7 -0.3,1.7 -0.3,2.4
  Top Layer region: -0.5,2.4 -0.5,1.7 -0.508,1.662 -0.529,1.629 -0.562,1.608 -0.6,1.6 -0.6,1.6 -0.638,1.608 -0.671,1.629 -0.692,1.662 -0.7,1.7 -0.7,1.7 -0.7,2.4
  Top Layer region: -0.9,2.4 -0.9,1.7 -0.908,1.662 -0.929,1.629 -0.962,1.608 -1,1.6 -1,1.6 -1.038,1.608 -1.071,1.629 -1.092,1.662 -1.1,1.7 -1.1,1.7 -1.1,2.4
  Top Layer region: -1.3,2.4 -1.3,1.7 -1.313,1.65 -1.35,1.613 -1.4,1.6 -1.4,1.6 -1.438,1.608 -1.471,1.629 -1.492,1.662 -1.5,1.7 -1.5,1.7 -1.5,2.4
  silkscreen extent -3.1,-2.07 2.07,2.07, body extent -2.5,-2.5 2.5,2.5, height 0.25
SC-74R [mm] "Diodes, Inc"
  rect 0.8x0.55 smd: 1(1.2,0.95) 2(1.2,0) 3(1.2,-0.95) 4(-1.2,-0.95) 5(-1.2,0) 6(-1.2,0.95)
  silkscreen extent -0.55,-1.55 0.55,1.55, body extent -1.42,-1.46 1.42,1.46, height 1.11
SMA [mm] "Molded Diode, 2-Leads, Body 4.3x2.6mm, IPC Medium Density, based on OnSemi component dimensions and land pattern"
  rect 2x2 smd: 1(-2,0) 2(2,0)
  silkscreen extent -3.66,-1.57 2.79,1.57, body extent -2.6,-1.3 2.6,1.3, height 2.42
SMA_Bi [mm] "SMD, 2-Leads, Body 4.275x2.575mm"
  rect 1.4x1.64 smd: 1(-2.015,0) 2(2.015,0)
  silkscreen extent -2.3,-1.45 2.3,1.45, body extent -2.52,-1.45 2.52,1.45, height 2.65
SNT-100-BK-G [mil] "Samtec STEP model"
  round 1 on Mech3: 0(0,0)
  body extent -100,-50 100,50, height 344
SOD-323 [mm] "NXP recommended land pattern"
  rect 0.6x0.6 smd paste-0.05: 1(-1.1,0) 2(1.1,0)
  silkscreen extent -2.06,-0.86 1.53,0.86, body extent -1.3,-0.67 1.3,0.68, height 1.1
SOT-23L [mm] "SOT23, 3-Leads, Body 2.9x1.3mm, Pitch 0.95mm, Lead Span 2.5mm, IPC High Density"
  rrect50% 0.8x0.6 smd: 1(-1.1,0.95) 2(-1.1,-0.95) 3(1.1,0)
  silkscreen extent -1.5,-1.5 0.7,1.5, body extent -1.16,-1.45 1.21,1.45, height 1
WEEE_Minimum [mil] "WEEElie bin"
  silkscreen extent -95,-172 99,104

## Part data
C1A C2A: library part CMP-0007449-4, "CAP, CERM, 330 pF, 50 V, +/- 10%, X7R, 0603", Cap_Case=0603, Manufacturer=MuRata, PartNumber=GRM188R71H331KA01D, Supplier Part Number 1=490-1486-1-ND, TempCo=X7R, Tolerance_%=10%, Value1=Unknown, Value2=50V, ValueDisplayed=330pF
C3A C4A C7A C20A: library part CMP-0011849-2, "CAP, TA, 33 uF, 35 V, +/- 20%, 0.065 ohm, SMD", Cap_Case=7343-31, Manufacturer=Kemet, Supplier Part Number 1=399-9786-1-ND, Tolerance_%=20%, Value1="0.065 ohm", Value2=35V, ValueDisplayed=33uF
C5A: library part CMP-0012121-3, "CAP, Aluminum Polymer, 47 uF, 25 V, +/- 20%, 0.03 ohm, F61 SMD", Manufacturer=Panasonic, PartNumber=25SVPF47M, Tolerance_%=20%, Value1="0.03 ohm", Value2=25V, ValueDisplayed=47uF
C6A C14A C17A C19A C31A C32A C33A C35A C36A C37A C38A C39A C41A C42A C46A: library part CMP-0007842-2, "CAP, CERM, 10 uF, 35 V, +/- 10%, X5R, 0805", Cap_Case=0805, Manufacturer=TDK, PartNumber=C2012X5R1V106K085AC, Supplier Part Number 1=445-14417-1-ND, TempCo=X5R, Tolerance_%=10%, Value1="0.002818 ohm", Value2=35V, ValueDisplayed=10uF
C8A C9A: library part CMP-0007433-4, "CAP, CERM, 0.01 uF, 50 V, +/- 10%, X7R, 0603", Cap_Case=0603, Manufacturer=MuRata, Supplier Part Number 1=490-1512-1-ND, TempCo=X7R, Tolerance_%=10%, Value1=Unknown, Value2=50V, ValueDisplayed=0.01uF
C10A: library part CMP-0006254-2, "CAP, CERM, 1000 pF, 50 V, +/- 5%, C0G/NP0, 0402", Cap_Case=0402, Manufacturer=TDK, Supplier Part Number 1=445-13785-1-ND, TempCo=C0G/NP0, Tolerance_%=5%, Value1=Unknown, Value2=50V, ValueDisplayed=1000pF
C11A C13A: library part CMP-0007423-4, "CAP, CERM, 0.047 uF, 25 V, +/- 10%, X7R, 0603", Cap_Case=0603, Manufacturer=MuRata, PartNumber=GRM188R71E473KA01D, Supplier Part Number 1=490-1522-1-ND, TempCo=X7R, Tolerance_%=10%, Value1=Unknown, Value2=25V, ValueDisplayed=0.047uF
C12A: library part CMP-0007356-5, "CAP, CERM, 2.2 uF, 35 V, +/- 10%, X5R, 0603", Cap_Case=0603, Manufacturer=MuRata, PartNumber=GRM188R6YA225KA12D, Supplier Part Number 1=490-7204-6-ND, TempCo=X5R, Tolerance_%=10%, Value1=Unknown, Value2=35V, ValueDisplayed=2.2uF
C15A: library part CMP-0007050-4, "CAP, CERM, 0.47 uF, 50 V, +/- 10%, X7R, 0603", Cap_Case=0603, Manufacturer=TDK, Supplier Part Number 1=445-5952-1-ND, TempCo=X7R, Tolerance_%=10%, Value1="0.010974 ohm", Value2=50V, ValueDisplayed=0.47uF
C16A C34A C49A: library part CMP-0007405-4, "CAP, CERM, 1 uF, 25 V, +/- 10%, X7R, 0603", Cap_Case=0603, Manufacturer=MuRata, PartNumber=GRM188R71E105KA12D, Supplier Part Number 1=490-5307-1-ND, TempCo=X7R, Tolerance_%=10%, Value1=Unknown, Value2=25V, ValueDisplayed=1uF
C18A: library part CMP-0085842-1, "CAP, CERM, 0.01 µF, 50 V,+/- 10%, X7R, 0402", Cap_Case=0402, Manufacturer=Walsin, TempCo=X7R, Tolerance_%=10%, Value2=50V, ValueDisplayed=0.01µF
C21A C25A C26A: library part CMP-0006196-2, "CAP, CERM, 100 pF, 50 V, +/- 1%, C0G/NP0, 0402", Cap_Case=0402, Manufacturer=AVX, Supplier Part Number 1=478-3658-1-ND, TempCo=C0G/NP0, Tolerance_%=1%, Value1=Unknown, Value2=50V, ValueDisplayed=100pF
C22A C23A C24A: library part CMP-0008965-2, "CAP, CERM, 10 uF, 25 V, +/- 10%, X7R, 1206", Cap_Case=2220, Manufacturer=MuRata, PartNumber=GRM31CR71E106KA12L, Supplier Part Number 1=81-GRM31CR71E106KA12, TempCo=X7R, Tolerance_%=10%, Value1=Unknown, Value2=25V, ValueDisplayed=10uF
C27A: library part CMP-0006454-2, "CAP, CERM, 33 pF, 50 V, +/- 5%, C0G/NP0, 0402", Cap_Case=0402, Manufacturer=MuRata, PartNumber=GRM1555C1H330JA01D, Supplier Part Number 1=81-GRM1555C1H330JA1D, TempCo=C0G/NP0, Tolerance_%=5%, Value1=Unknown, Value2=50V, ValueDisplayed=33pF
C28A: library part CMP-0006420-2, "CAP, CERM, 15 pF, 50 V, +/- 5%, C0G/NP0, 0402", Cap_Case=0402, Manufacturer=MuRata, PartNumber=GRM1555C1H150JA01D, Supplier Part Number 1=81-GRM1555C1H150JA1D, TempCo=C0G/NP0, Tolerance_%=5%, Value1=Unknown, Value2=50V, ValueDisplayed=15pF
C29A: library part CMP-0006688-2, "CAP, CERM, 3300 pF, 50 V, +/- 10%, X7R, 0402", Cap_Case=0402, Manufacturer=MuRata, Supplier Part Number 1=490-3248-1-ND, TempCo=X7R, Tolerance_%=10%, Value1=Unknown, Value2=50V, ValueDisplayed=3300pF
C30A: library part CMP-0006240-2, "CAP, CERM, 1200 pF, 50 V, +/- 5%, C0G/NP0, 0402", Cap_Case=0402, Manufacturer=Kemet, Supplier Part Number 1=399-7334-1-ND, TempCo=C0G/NP0, Tolerance_%=5%, Value1=Unknown, Value2=50V, ValueDisplayed=1200pF
C40A C50A C51A: library part CMP-0860983-1, "CAP, CERM, 0.1 µF, 50 V,+/- 10%, X7R, 0402", Cap_Case=0402, Manufacturer="Passive Plus", TempCo=X7R, Tolerance_%=10%, Value2=50V, ValueDisplayed=0.1µF
C43A C44A: library part CMP-0006329-2, "CAP, CERM, 0.033 uF, 50 V, +/- 10%, X7R, AEC-Q200 Grade 1, 0402", Cap_Case=0402, Manufacturer=TDK, Supplier Part Number 1=445-6896-1-ND, TempCo=X7R, Tolerance_%=10%, Value1="0.098477 ohm", Value2=50V, ValueDisplayed=0.033uF
C45A C48A: library part CMP-0006681-2, "CAP, CERM, 0.018 uF, 50 V, +/- 10%, X7R, 0402", Cap_Case=0402, Manufacturer=MuRata, Supplier Part Number 1=GRM155R71H183KA12D-ND, TempCo=X7R, Tolerance_%=10%, Value1=Unknown, Value2=50V, ValueDisplayed=0.018uF
C47A: library part CMP-0006331-2, "CAP, CERM, 0.068 uF, 50 V, +/- 10%, X7R, AEC-Q200 Grade 1, 0402", Cap_Case=0402, Manufacturer=TDK, Supplier Part Number 1=445-6898-1-ND, TempCo=X7R, Tolerance_%=10%, Value1="0.05606 ohm", Value2=50V, ValueDisplayed=0.068uF
D1A: library part CMP-0002827-3, "LED, Green, SMD", Color=green, Manufacturer=Lite-On, Power_TotalModule=100mW, Value1=0.1W, Value2=2.1V
D2A: library part CMP-0028399-2, "Diode, Schottky, 20 V, 2 A, SMA", Manufacturer="Diodes Inc.", PartNumber=B220A-13-F, Value1=2A, Value2=0.5V
D3A D4A: library part CMP-0028455-2, "Diode, Schottky, 30 V, 0.2 A, SOD-323", Manufacturer="ON Semiconductor", Value1=0.2A, Value2=0.35V
J1A J2A J3A: library part CMP-0074910-1, "Terminal Block, 5.08 mm, 2x1, Brass, TH", Color=Blue, Current_A=15A, Manufacturer="On-Shore Technology", PartNumber=ED120/2DS, Supplier Part Number 1=ED1609-ND, Voltage_V=300V
J4A: library part CMP-0089047-2, "Connector Header Through Hole, Right Angle 4 position 0.100\" (2.54mm)", Current_A=4A, Manufacturer=Molex, PartNumber=0022053041, Voltage_V=500V
J5A: library part CMP-0055135-1, "Shorting Jumper, 5.375mm, 2 Position, Tin, SMT", Color=Silver, Manufacturer=Keystone, Supplier Part Number 1=36-5102-ND
JP1A JP2A: library part CMP-0054947-1, "Header, 100mil, 2x1, Gold, TH", Manufacturer="TE Connectivity", PartNumber=5-146261-1
L1A: library part CMP-0088941-1, "2.2µH Shielded Wirewound Inductor 13A 9mOhm Max 10x10x3mm", Manufacturer="Chilisin Electronics", Operating Temperature Range="-55°C to +125°C", Part Number=BMRHDY1010302R2MA1, Test Frequency=100kHz, Tolerance_%=20%
Logo1: library part CMP-0074847-1, "FCC_disclaimer"
LOGO3: library part CMP-0074837-1, "IEC 61010-1 Hot Surface Warning"
Logo4: library part CMP-0074769-1
LOGO5: library part CMP-0074844-1
Q1A Q2A: library part CMP-0000606-2, "MOSFET, 2-CH, N-CH, 30 V, 45 A, DQY0008A (LSON-CLIP-8)", Alternate Manufacturer=None, Manufacturer="Texas Instruments", Supplier Part Number 1=296-44041-1-ND, Value1=0.004, Value2="10.5 nC"
Q3A: library part CMP-0088961-1, "MOSFET P-CH 30V 3X3 DFN", Digikey Part Number=785-1796-1-ND, Drain To Source Breakdown Voltage=-30V, Input Capacitace At Vds="1995pF @ -15V", Manufacturer="Alpha & Omega Semiconductor", Operating Temperature Range="-55°C to +150°C", Power_W=5W, Pulse Drain Current=-82A, Typ Forward Diode Voltage=-0.7V
Q4A Q5A: library part CMP-0000772-1, "MOSFET, N-CH, 60 V, 0.26 A, SOT-23", Alternate Manufacturer=None, Manufacturer="ON Semiconductor", PartNumber=2N7002ET1G, Supplier Part Number 1=2N7002ET1GOSCT-ND, Value2="0.81 nC"
Q6A: library part CMP-0000514-2, "Transistor, NPN/PNP Pair, 50 V, 0.05 A, SC-74R", Manufacturer="Diodes Inc.", Supplier Part Number 1=DCX124EK-FDICT-ND, Value1="0.05 A", Value2=600
Q7A Q8A: library part CMP-0000041-3, "MOSFET, P-CH, -30 V, -8.5 A, AEC-Q101, 8-PowerVDFN", Alternate Manufacturer=None, Manufacturer="Diodes Inc.", Value2="35.5 nC"
R1A: library part CMP-0022268-4, "RES, 2.00 k, 1%, 0.1 W, AEC-Q200 Grade 0, 0603", Manufacturer=Vishay-Dale, PartNumber=CRCW06032K00FKEA, Power_W=100mW, Supplier Part Number 1=541-2.00KHCT-ND, TempCo="100 ppm/C", Tolerance_%=1%, Value2=0.1W, Value_Code=2k00, ValueDisplayed=2.00k
R2A R3A: library part CMP-0025829-4, "RES, 56, 5%, 0.1 W, AEC-Q200 Grade 0, 0603", Manufacturer=Vishay-Dale, PartNumber=CRCW060356R0JNEA, Power_W=100mW, Supplier Part Number 1=541-56GCT-ND, TempCo="200 ppm/C", Tolerance_%=5%, Value2=0.1W, Value_Code=56R0, ValueDisplayed=56
R4A: library part CMP-0084411-1, "RES, 0.005, 1%, 1 W, AEC-Q200 Grade 0, 1206", Manufacturer=Vishay-Dale, Power_W=1W, TempCo="110 ppm/C", Tolerance_%=1%, Value_Code=5L000, ValueDisplayed=0.005
R5A R7A: library part CMP-0026434-2, "RES, 4.99, 1%, 0.063 W, AEC-Q200 Grade 0, 0402", Manufacturer=Vishay-Dale, Power_W=63mW, Supplier Part Number 1=541-4.99LLCT-ND, TempCo="100 ppm/C", Tolerance_%=1%, Value2=0.063W, Value_Code=4R99, ValueDisplayed=4.99
R6A: library part CMP-0016512-2, "RES, 0.005, 1%, 1.5 W, 2010", Manufacturer="Stackpole Electronics Inc", Power_W=1.5W, Supplier Part Number 1=CSNL2010FT5L00CT-ND, TempCo="50 ppm/C", Tolerance_%=1%, Value_Code=5L000, ValueDisplayed=0.005
R8A R9A R30A: library part CMP-0025963-3, "RES, 10.0, 1%, 0.063 W, AEC-Q200 Grade 0, 0402", Manufacturer=Vishay-Dale, Power_W=63mW, Supplier Part Number 1=541-10.0LCT-ND, TempCo="100 ppm/C", Tolerance_%=1%, Value2=0.063W, Value_Code=10R0, ValueDisplayed=10.0
R10A: library part CMP-0026728-1, "RES, 220 k, 1%, 0.0625 W, 0402", Manufacturer="Yageo America", Power_W=62.5mW, Supplier Part Number 1=311-220KLRCT-ND, TempCo="100 ppm/C", Tolerance_%=1%, Value2=0.0625W, Value_Code=220k
R11A: library part CMP-0025958-3, "RES, 10.0 k, 1%, 0.063 W, AEC-Q200 Grade 0, 0402", Manufacturer=Vishay-Dale, PartNumber=CRCW040210K0FKED, Power_W=63mW, Supplier Part Number 1=541-10.0KLCT-ND, TempCo="100 ppm/C", Tolerance_%=1%, Value2=0.063W, Value_Code=10k0, ValueDisplayed=10.0k
R12A: library part CMP-0026042-3, "RES, 16.9 k, 1%, 0.063 W, AEC-Q200 Grade 0, 0402", Manufacturer=Vishay-Dale, Power_W=63mW, Supplier Part Number 1=541-16.9KLCT-ND, TempCo="100 ppm/C", Tolerance_%=1%, Value2=0.063W, Value_Code=16k9, ValueDisplayed=16.9k
R13A: library part CMP-0025954-3, "RES, 105 k, 1%, 0.063 W, AEC-Q200 Grade 0, 0402", Manufacturer=Vishay-Dale, Power_W=63mW, Supplier Part Number 1=541-105KLCT-ND, TempCo="100 ppm/C", Tolerance_%=1%, Value2=0.063W, Value_Code=105k
R14A R23A R29A R32A R33A: library part CMP-0025950-3, "RES, 100 k, 1%, 0.063 W, AEC-Q200 Grade 0, 0402", Manufacturer=Vishay-Dale, Power_W=63mW, Supplier Part Number 1=541-100KLCT-ND, TempCo="100 ppm/C", Tolerance_%=1%, Value2=0.063W, Value_Code=100k
R15A: library part CMP-0026284-2, "RES, 30.1 k, 1%, 0.063 W, AEC-Q200 Grade 0, 0402", Manufacturer=Vishay-Dale, Power_W=63mW, Supplier Part Number 1=541-30.1KLCT-ND, TempCo="100 ppm/C", Tolerance_%=1%, Value2=0.063W, Value_Code=30k1, ValueDisplayed=30.1k
R16A R17A R18A R25A R26A R34A R35A: library part CMP-0025958-3, "RES, 10.0 k, 1%, 0.063 W, AEC-Q200 Grade 0, 0402", Manufacturer=Vishay-Dale, Power_W=63mW, Supplier Part Number 1=541-10.0KLCT-ND, TempCo="100 ppm/C", Tolerance_%=1%, Value2=0.063W, Value_Code=10k0, ValueDisplayed=10.0k
R19A R36A: library part CMP-0017299-3, "RES, 10.0, 1%, 0.25 W, AEC-Q200 Grade 0, 1206", Manufacturer=Panasonic, Power_W=250mW, Supplier Part Number 1=P10.0FCT-ND, TempCo="100 ppm/C", Tolerance_%=1%, Value2=0.25W, Value_Code=10R0, ValueDisplayed=10.0
R20A R21A: library part CMP-0018679-3, "RES, 3.9, 5%, 0.25 W, AEC-Q200 Grade 0, 1206", Manufacturer=Vishay-Dale, PartNumber=CRCW12063R90JNEA, Power_W=250mW, Supplier Part Number 1=541-3.9ECT-ND, TempCo="200 ppm/C", Tolerance_%=5%, Value2=0.25W, Value_Code=3R90
R22A: library part CMP-0022204-4, "RES, 20.0 k, 1%, 0.1 W, AEC-Q200 Grade 0, 0603", Manufacturer=Vishay-Dale, Power_W=100mW, Supplier Part Number 1=541-20.0KHCT-ND, TempCo="100 ppm/C", Tolerance_%=1%, Value2=0.1W, Value_Code=20k0, ValueDisplayed=20.0k
R24A: library part CMP-0025743-4, "RES, 1.0, 5%, 0.1 W, AEC-Q200 Grade 0, 0603", Manufacturer=Vishay-Dale, Power_W=100mW, Supplier Part Number 1=541-1.0GCT-ND, TempCo="200 ppm/C", Tolerance_%=5%, Value2=0.1W, Value_Code=1R00, ValueDisplayed=1.0
R27A: library part CMP-0026321-2, "RES, 383 k, 1%, 0.063 W, AEC-Q200 Grade 0, 0402", Manufacturer=Vishay-Dale, Power_W=63mW, Supplier Part Number 1=541-383KLCT-ND, TempCo="100 ppm/C", Tolerance_%=1%, Value2=0.063W, Value_Code=383k
R28A: library part CMP-0078584-1, "RES, 33.0 k, 1%, 0.063 W, 0402", Manufacturer="Yageo America", Power_W=63mW, Supplier Part Number 1=311-33.0KLRCT-ND, TempCo="100 ppm/C", Tolerance_%=1%, Value2=0.063W, Value_Code=33k0, ValueDisplayed=33.0k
